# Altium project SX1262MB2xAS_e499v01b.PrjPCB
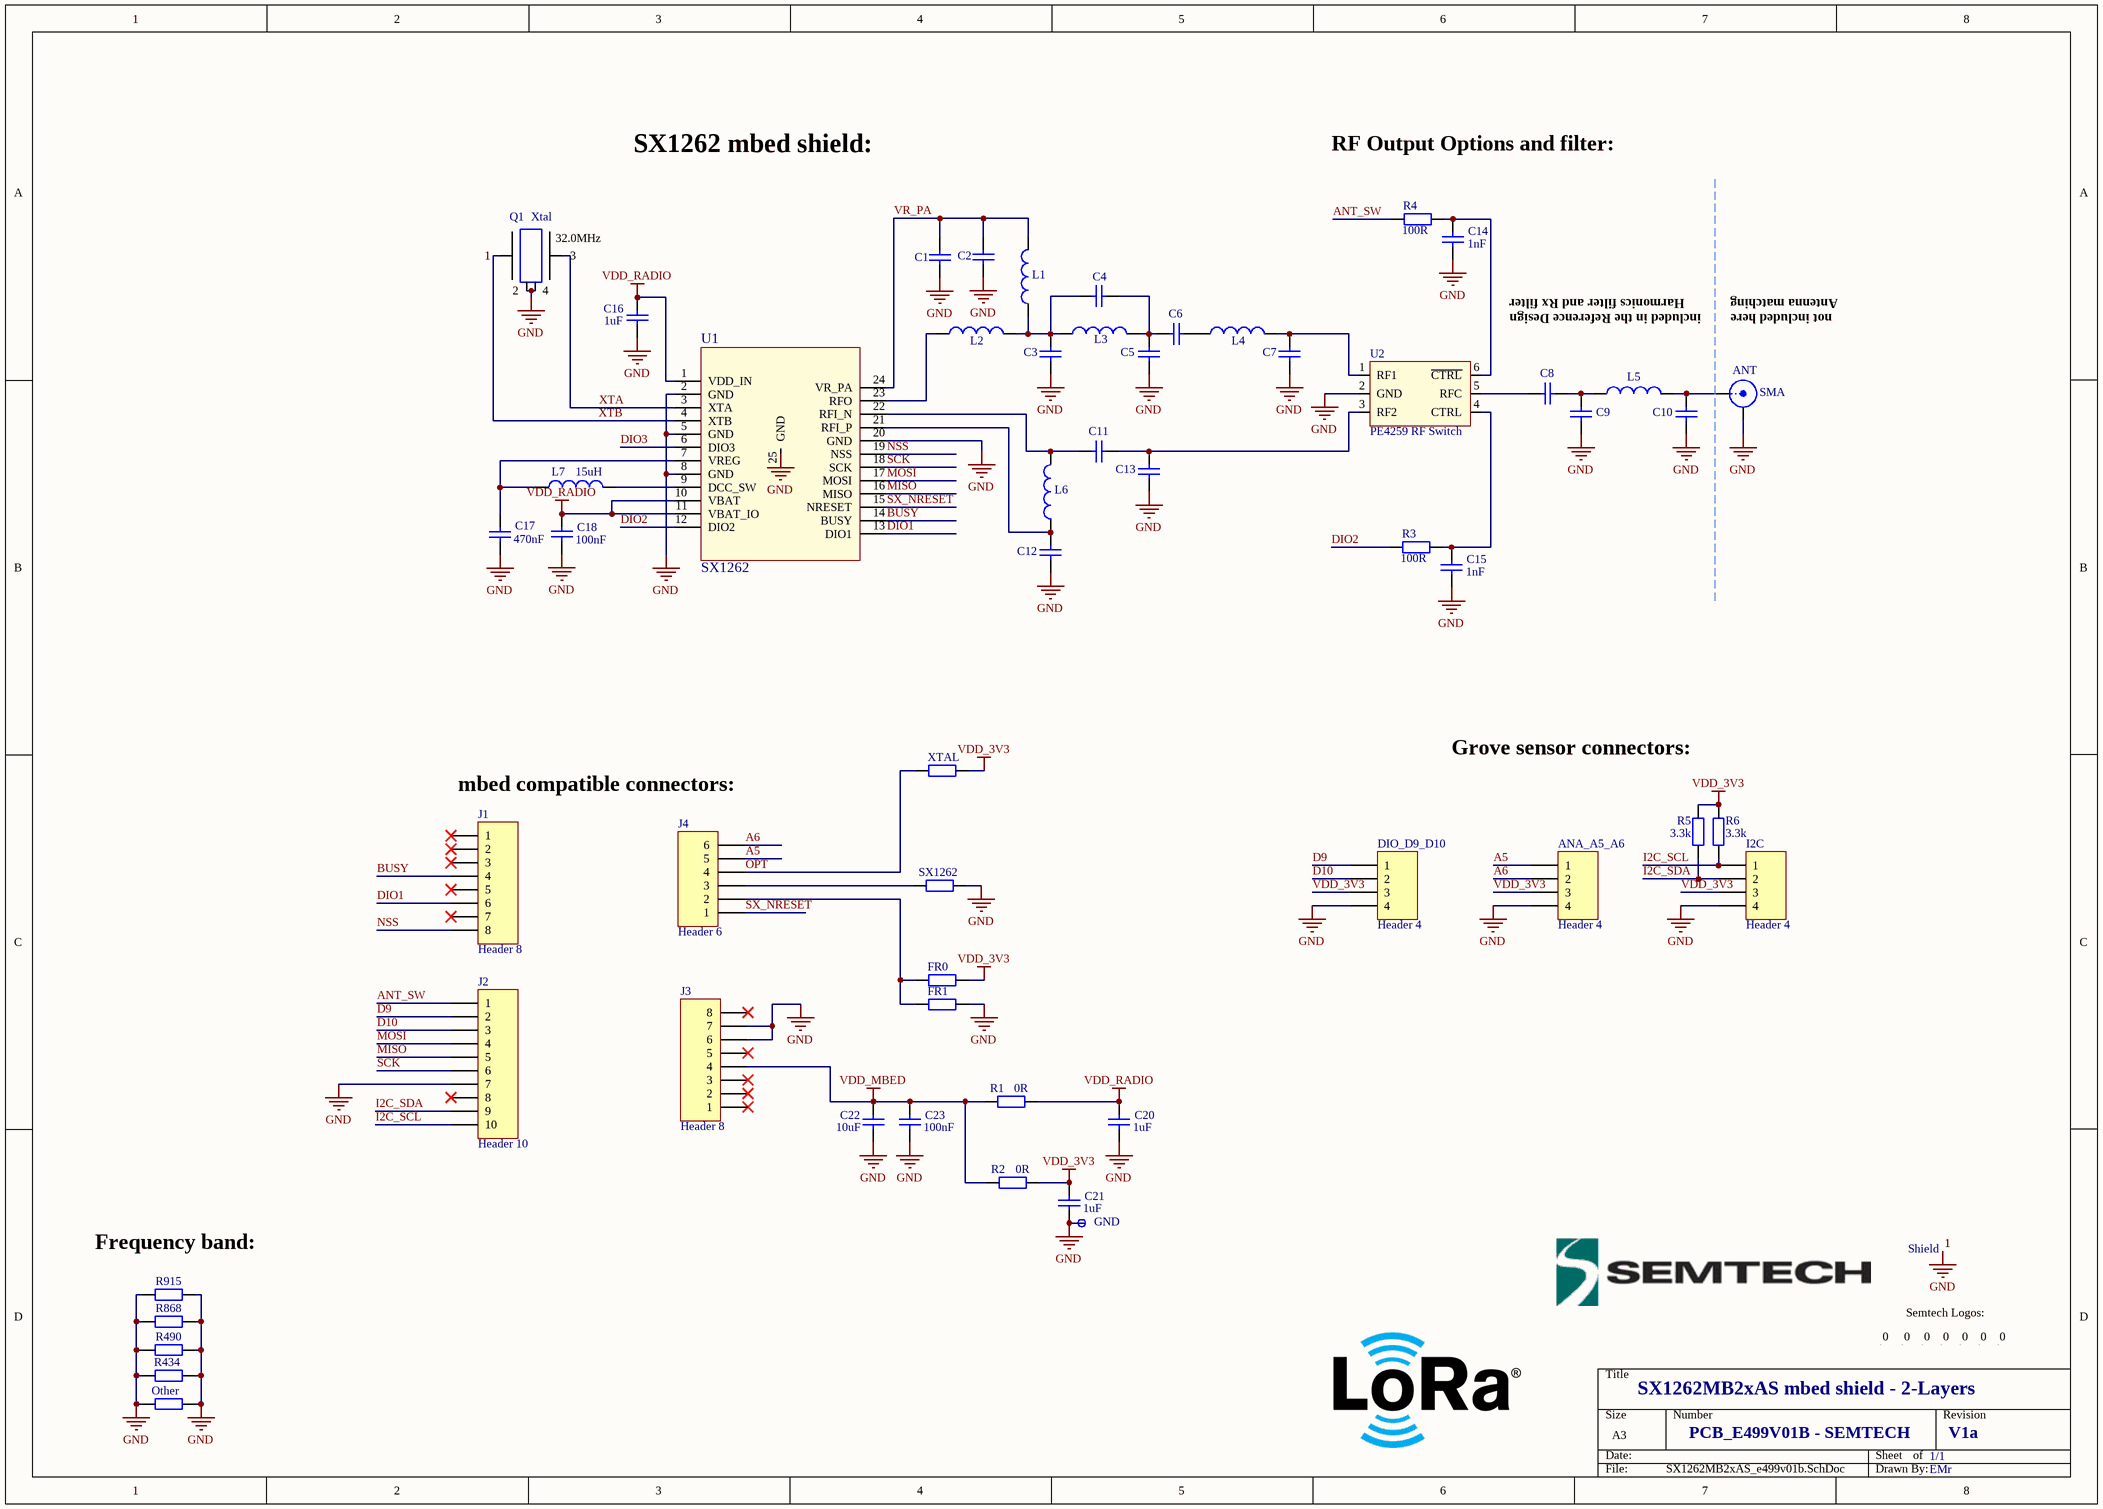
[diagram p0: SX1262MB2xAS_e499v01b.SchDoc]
1 sheet, 64 parts. Net scope: global (net labels, ports and power ports of the same name join across sheets).
Board file: SX1262MB2xAS_e499v01b.PcbDoc

## Sheet SX1262MB2xAS_e499v01b.SchDoc
size A3; DocumentNumber: 1; SheetNumber: 1; SheetTotal: 2

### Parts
ANA_A5_A6  Header 4  [1125S-4P_connector]
ANT  SMA  [SMA_end_launch_1.0mm_9.52mm]
C1  Cap  [rlc_402_smd]  (value not drawn)
C2  Cap  [rlc_402_smd]  (value not drawn)
C3  Cap  [rlc_402_smd]  (value not drawn)
C4  Cap  [rlc_402_smd]  (value not drawn)
C5  Cap  [rlc_402_smd]  (value not drawn)
C6  Cap  [rlc_402_smd]  (value not drawn)
C7  Cap  [rlc_402_smd]  (value not drawn)
C8  Cap  [rlc_402_smd]  (value not drawn)
C9  Cap  [rlc_402_smd]  (value not drawn)
C10  Cap  [rlc_402_smd]  (value not drawn)
C11  Cap  [rlc_402_smd]  (value not drawn)
C12  Cap  [rlc_402_smd]  (value not drawn)
C13  Cap  [rlc_402_smd]  (value not drawn)
C14  value 1nF  [rlc_402_smd]  (hidden comment: Cap)
C15  value 1nF  [rlc_402_smd]  (hidden comment: Cap)
C16  value 1uF  [rlc_402_smd]  (hidden comment: Cap)
C17  value 470nF  [rlc_402_smd]  (hidden comment: Cap)
C18  value 100nF  [rlc_402_smd]  (hidden comment: Cap)
C20  value 1uF  [rlc_603_smd]  (hidden comment: Cap)
C21  value 1uF  [rlc_603_smd]  (hidden comment: Cap)
C22  value 10uF  [rlc_805_smd]  (hidden comment: Cap)
C23  value 100nF  [rlc_402_smd]  (hidden comment: Cap)
DIO_D9_D10  Header 4  [1125S-4P_connector]
FR0  Resistor  [rlc_402_smd]  (value not drawn)
FR1  Resistor  [rlc_402_smd]  (value not drawn)
GND  Test Pin  [pin_0.9mm]  (value not drawn)
I2C  Header 4  [1125S-4P_connector]
J1  Header 8  [HDR1X8]
J2  Header 10  [HDR1X10]
J3  Header 8  [HDR1X8]
J4  Header 6  [HDR1X6]
L1  Inductor  [rlc_402_smd]  (value not drawn)
L2  Inductor  [rlc_402_smd]  (value not drawn)
L3  Inductor  [rlc_402_smd]  (value not drawn)
L4  Inductor  [rlc_402_smd]  (value not drawn)
L5  Inductor  [rlc_402_smd]  (value not drawn)
L6  Inductor  [rlc_402_smd]  (value not drawn)
L7  value 15uH  [rlc_805_smd enlarged]  (hidden comment: Inductor)
Logo_Bot1  Logo symbol  [Logo LoRa Size4]  (value not drawn)
Logo_ESD1  Logo symbol  [Logo ESD]  (value not drawn)
Logo_LoRA_Top1  Logo symbol  [Logo LoRa Size4]  (value not drawn)
Logo_mbed1  Logo symbol  [logo mbed 2]  (value not drawn)
Logo_Recycling1  Logo symbol  [Logo Recycling1]  (value not drawn)
Logo_Semtech1  Logo symbol  [logo_semtech_horiz_size4]  (value not drawn)
Logo_Semtech_1  Logo symbol  [logo_semtech_horiz_size3]  (value not drawn)
Other  Resistor  [rlc_402_smd]  (value not drawn)
Q1  Xtal  value 32.0MHz  [nd2016da]
R1  value 0R  [rlc_603_smd]  (hidden comment: Resistor)
R2  value 0R  [rlc_603_smd]  (hidden comment: Resistor)
R3  value 100R  [rlc_402_smd]  (hidden comment: Resistor)
R4  value 100R  [rlc_402_smd]  (hidden comment: Resistor)
R5  value 3.3k  [rlc_402_smd]  (hidden comment: Resistor)
R6  value 3.3k  [rlc_402_smd]  (hidden comment: Resistor)
R434  Resistor  [rlc_402_smd]  (value not drawn)
R490  Resistor  [rlc_402_smd]  (value not drawn)
R868  Resistor  [rlc_402_smd]  (value not drawn)
R915  Resistor  [rlc_402_smd]  (value not drawn)
Shield  Logo symbol  [BMIS-209-F - Shield]  (value not drawn)
SX1262  Resistor  [rlc_402_smd]  (value not drawn)
U1  SX1262  [vqfn24_4x4mm]
U2  PE4259 RF Switch  [SC70-6]
XTAL  Resistor  [rlc_402_smd]  (value not drawn)

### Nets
GND: ANA_A5_A6.4 ANT.2(GND) C1.1 C2.1 C3.1 C5.1 C7.1 C9.1 C10.1 C12.1 C13.1 C14.2 C15.2 C16.1 C17.1 C18.1 C20.1 C21.1 C22.1 C23.1 DIO_D9_D10.4 FR1.1 GND.1(pin) I2C.4 J2.7 J3.6 J3.7 Other.1 Other.2 Q1.2 Q1.4 R434.1 R434.2 R490.1 R490.2 R868.1 R868.2 R915.1 R915.2 Shield.1 SX1262.1 U1.2(GND) U1.5(GND) U1.8(GND) U1.20(GND) U1.25(GND) U2.2(GND)
VDD_3V3: ANA_A5_A6.3 C21.2 DIO_D9_D10.3 FR0.1 I2C.3 R2.1 R5.2 R6.2 XTAL.1
VDD_MBED: C22.2 C23.2 J3.4 R1.2 R2.2
VDD_RADIO: C16.2 C18.2 C20.2 R1.1 U1.1(VDD_IN) U1.10(VBAT) U1.11(VBAT_IO)
A5: ANA_A5_A6.1 J4.5
A6: ANA_A5_A6.2 J4.6
ANT_SW: J2.1 R4.2
BUSY: J1.4 U1.14(BUSY)
D9: DIO_D9_D10.1 J2.2
D10: DIO_D9_D10.2 J2.3
DIO1: J1.6 U1.13(DIO1)
DIO2: R3.2 U1.12(DIO2)
DIO3: U1.6(DIO3)
I2C_SCL: I2C.1 J2.10 R6.1
I2C_SDA: I2C.2 J2.9 R5.1
MISO: J2.5 U1.16(MISO)
MOSI: J2.4 U1.17(MOSI)
NSS: J1.8 U1.19(NSS)
OPT: J4.4 XTAL.2
SCK: J2.6 U1.18(SCK)
SX_NRESET: J4.1 U1.15(NRESET)
VR_PA: C1.2 C2.2 L1.2 U1.24(VR_PA)
XTA: Q1.3 U1.3(XTA)
XTB: Q1.1 U1.4(XTB)
NetANT_1: ANT.1(Signal) C10.2 L5.2
NetC3_2: C3.2 C4.2 L1.1 L2.2 L3.1
NetC4_1: C4.1 C5.2 C6.2 L3.2
NetC6_1: C6.1 L4.1
NetC7_2: C7.2 L4.2 U2.1(RF1)
NetC8_1: C8.1 C9.2 L5.1
NetC8_2: C8.2 U2.5(RFC)
NetC11_1: C11.1 C13.2 U2.3(RF2)
NetC11_2: C11.2 L6.2 U1.22(RFI_N)
NetC12_2: C12.2 L6.1 U1.21(RFI_P)
NetC14_1: C14.1 R4.1 U2.6(~{CTRL})
NetC15_1: C15.1 R3.1 U2.4(CTRL)
NetC17_2: C17.2 L7.1 U1.7(VREG)
NetFR0_2: FR0.2 FR1.2 J4.2
NetJ4_3: J4.3 SX1262.2
NetL2_1: L2.1 U1.23(RFO)
NetL7_2: L7.2 U1.9(DCC_SW)

Not connected (* = marked no-connect by the designer): J1 1* 2* 3* 5* 7*; J2 8*; J3 1* 2* 3* 5* 8*; Logo_Bot1 0; Logo_ESD1 0; Logo_LoRA_Top1 0; Logo_mbed1 0; Logo_Recycling1 0; Logo_Semtech1 0; Logo_Semtech_1 0

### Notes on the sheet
- SX1262 mbed shield:
- RF Output Options and filter:
- Harmonics filter and Rx filter
- included in the Reference Design
- not included here
- Antenna matching
- Grove sensor connectors:
- mbed compatible connectors:
- (near R915) Frequency band:
- Semtech Logos:
- SX1262MB2xAS mbed shield - 2-Layers
- PCB_E499V01B - SEMTECH
- 1/1
- V1a
- EMr

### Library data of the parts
ANA_A5_A6 DIO_D9_D10 I2C = Header 4: Header, 4-Pin
ANT = SMA: SMA Straight Connector
C1-C13 = Cap: Capacitor SMD; Value: NC
C14-C18 C20-C23 = Cap: Capacitor SMD
FR0 XTAL = Resistor: Resistor SMD - IEC symbol version; Value: 1k
FR1 Other R434 R490 R868 R915 = Resistor: Resistor SMD - IEC symbol version; Value: NC
GND = test_pin
J1 J3 = Header 8: Header, 8-Pin
J2 = Header 10: Header, 10-Pin
J4 = Header 6: Header, 6-Pin
L1-L6 = Inductor: Inductor SMD; Code_IEC: 1005; Value: 0R
L7 = Inductor: Inductor SMD; Code_IEC: 1005
Logo_Bot1 Logo_ESD1 Logo_LoRA_Top1 Logo_mbed1 Logo_Recycling1 Logo_Semtech1 Logo_Semtech_1 = Logo: Schematic symbol for Logo
Q1 = Xtal GND: Crystal with GND pins
R1-R6 = Resistor: Resistor SMD - IEC symbol version
Shield = Shield: Shield - EMI Gasket - Standard Surface Mount Shields
SX1262 = Resistor: Resistor SMD - IEC symbol version; Value: 10k
U1 = SX126x: SX1262- Ultra low power RF transceiver
U2 = PE4259 RF Switch: PE4259 Peregrine RF Switch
